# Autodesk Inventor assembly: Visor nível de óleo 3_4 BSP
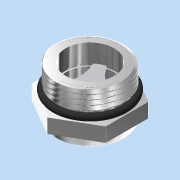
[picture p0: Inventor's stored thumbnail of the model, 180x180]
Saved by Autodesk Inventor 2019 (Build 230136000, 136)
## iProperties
Created: 2019-10
Part Number: Visor nível de óleo 3_4 BSP
Material: Genérico
Document SubType Name: Assembly
Designer: Marcos
Author: Marcos
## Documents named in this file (6)
- C:\Users\Usuario\Desktop\Visor de óleo\Visor nível de óleo 3_4 BSP.iam
- C:\Users\Usuario\Desktop\Visor de óleo\DIfusor de pressão.ipt
- C:\Users\Usuario\Desktop\Visor de óleo\Lente de vidro 23mm.ipt
- C:\Users\Usuario\Desktop\Visor de óleo\Vedação 2.ipt
- C:\Users\Usuario\Desktop\Visor de óleo\Vedação.ipt
- C:\Users\Usuario\Desktop\Visor de óleo\Visor de nível 3-4 bsp (corpo).ipt
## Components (5 placed, 5 different names)
1. Visor de nível 3-4 bsp (corpo):1 — Coincidência:1, Coincidência:2, Coincidência:3, Coincidência:5, Coincidência:6, Coincidência:7, Tangente:1
2. DIfusor de pressão:1 — Coincidência:5, Coincidência:6
3. Lente de vidro 23mm:1 — Coincidência:3, Coincidência:4
4. Vedação 2:1 — Coincidência:7, Tangente:1
5. Vedação:1 — Coincidência:1, Coincidência:2, Coincidência:4
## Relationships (8: Mate 7, Tangent 1)
- Coincidência:1 [Mate]: Visor de nível 3-4 bsp (corpo):1 ↔ Vedação:1
- Coincidência:2 [Mate]: Visor de nível 3-4 bsp (corpo):1 ↔ Vedação:1
- Coincidência:3 [Mate]: Visor de nível 3-4 bsp (corpo):1 ↔ Lente de vidro 23mm:1
- Coincidência:4 [Mate]: Lente de vidro 23mm:1 ↔ Vedação:1
- Coincidência:5 [Mate]: Visor de nível 3-4 bsp (corpo):1 ↔ DIfusor de pressão:1
- Coincidência:6 [Mate]: Visor de nível 3-4 bsp (corpo):1 ↔ DIfusor de pressão:1
- Coincidência:7 [Mate]: Visor de nível 3-4 bsp (corpo):1 ↔ Vedação 2:1
- Tangente:1: Visor de nível 3-4 bsp (corpo):1 ↔ Vedação 2:1
